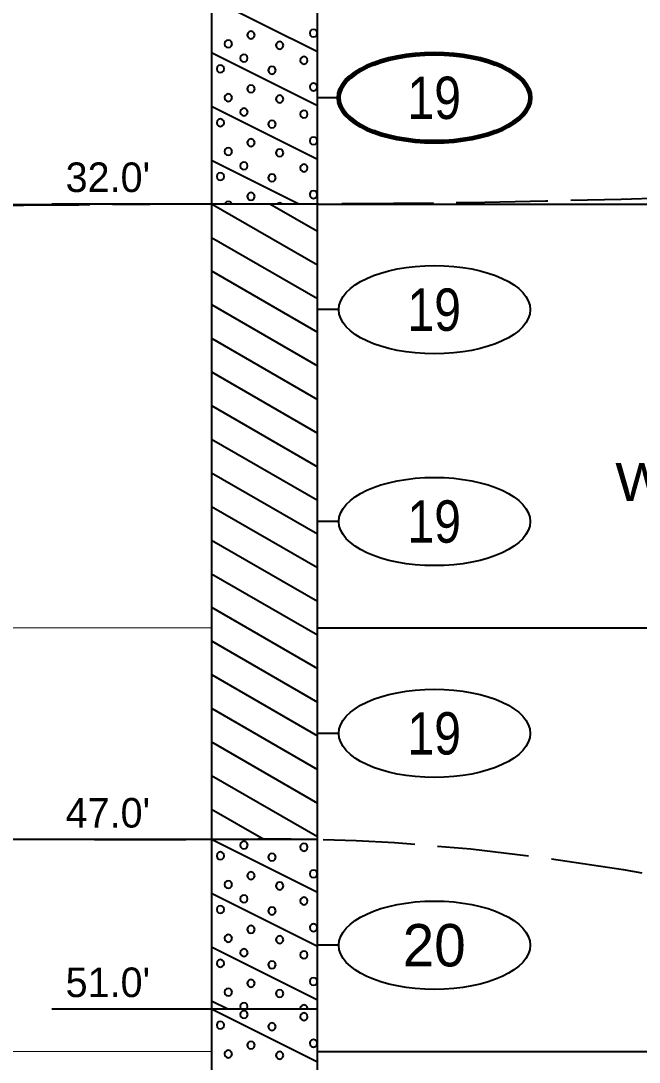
# Model space of a CAD drawing. Extents: x -76 to 974, y -1080 to -735.
# Drawn here: x 281.69 to 296.27, y -982.34 to -957.76 of the extents above; entities that cross this region are included whole.
import ezdxf
from ezdxf.enums import TextEntityAlignment as Align

# ---------------------------------------------------------------- set-up
doc = ezdxf.new("R2010")
doc.units = 0
doc.header["$LTSCALE"] = 0.36
doc.linetypes.add('LONG_DASHED', pattern=[7.5, 6, -1.5])
for name, color, linetype, lineweight in [('27', 7, 'Continuous', 40), ('28', 7, 'LONG_DASHED', 60), ('7', 7, 'Continuous', 13)]:
    doc.layers.add(name, color=color, linetype=linetype, lineweight=lineweight)
doc.layers.add('29', color=7, linetype='Continuous')

msp = doc.modelspace()

# ---------------------------------------------------------------- linework, layer by layer
at = {"layer": '27'}
for p, q in [((286.1855, -947.0789), (286.1855, -962.0789)), ((288.6855, -962.0789), (288.6855, -947.0789)), ((286.1855, -957.2389), (288.6855, -958.4889)), ((286.1855, -958.5089), (288.6855, -959.7589)), ((289.1855, -959.5789), (288.6855, -959.5789)), ((286.1855, -959.7789), (288.6855, -961.0289)), ((286.1855, -961.0489), (288.2455, -962.0789)), ((282.4181, -962.0789), (286.1855, -962.0789)), ((286.1855, -962.0789), (288.6855, -962.0789)), ((286.1855, -962.0789), (288.6855, -963.5223)), ((286.1855, -962.0789), (286.1855, -977.0789)), ((287.5603, -962.0789), (288.6855, -962.7286)), ((287.5603, -962.0789), (288.6855, -962.7286)), ((288.6855, -977.0789), (288.6855, -962.0789)), ((288.6855, -962.09), (321.1855, -962.09)), ((286.1855, -962.8727), (288.6855, -964.3161)), ((286.1855, -962.8727), (288.6855, -964.3161)), ((286.1855, -963.6664), (288.6855, -965.1098)), ((286.1855, -964.4602), (288.6855, -965.9036)), ((286.1855, -964.4602), (288.6855, -965.9036)), ((289.1855, -964.5789), (288.6855, -964.5789)), ((286.1855, -965.2539), (288.6855, -966.6973)), ((286.1855, -966.0477), (288.6855, -967.4911)), ((286.1855, -966.0477), (288.6855, -967.4911)), ((286.1855, -966.8414), (288.6855, -968.2848)), ((286.1855, -967.6352), (288.6855, -969.0786)), ((286.1855, -967.6352), (288.6855, -969.0786)), ((286.1855, -968.4289), (288.6855, -969.8723)), ((286.1855, -969.2227), (288.6855, -970.6661)), ((286.1855, -969.2227), (288.6855, -970.6661)), ((289.1855, -969.5789), (288.6855, -969.5789)), ((286.1855, -970.0164), (288.6855, -971.4598)), ((286.1855, -970.8102), (288.6855, -972.2536)), ((286.1855, -970.8102), (288.6855, -972.2536)), ((286.1855, -971.6039), (288.6855, -973.0473)), ((288.6855, -972.09), (321.1855, -972.09)), ((286.1855, -972.3977), (288.6855, -973.8411)), ((286.1855, -972.3977), (288.6855, -973.8411)), ((286.1855, -973.1914), (288.6855, -974.6348)), ((286.1855, -973.9852), (288.6855, -975.4286)), ((286.1855, -973.9852), (288.6855, -975.4286)), ((289.1855, -974.5789), (288.6855, -974.5789)), ((286.1855, -974.7789), (288.6855, -976.2223)), ((286.1855, -975.5727), (288.6855, -977.0161)), ((286.1855, -975.5727), (288.6855, -977.0161)), ((286.1855, -976.3664), (287.4196, -977.0789)), ((282.4181, -977.0789), (286.1855, -977.0789)), ((286.1855, -977.0789), (288.6855, -977.0789)), ((286.1855, -977.0789), (288.6855, -978.3289)), ((286.1855, -977.0789), (286.1855, -981.0789)), ((288.6855, -981.0789), (288.6855, -977.0789)), ((286.1855, -978.3489), (288.6855, -979.5989)), ((286.1855, -979.6189), (288.6855, -980.8689)), ((289.1855, -979.5789), (288.6855, -979.5789)), ((282.4181, -981.0789), (286.1855, -981.0789)), ((286.1855, -980.8889), (286.5655, -981.0789)), ((286.1855, -981.0789), (288.6855, -981.0789)), ((286.1855, -981.0789), (288.6855, -982.3289)), ((286.1855, -981.0789), (286.1855, -987.0789)), ((288.6855, -987.0789), (288.6855, -981.0789)), ((288.6855, -982.09), (321.1855, -982.09))]:
    msp.add_line(p, q, dxfattribs=at)
for points in [[(288.6773, -958.0542), (288.6654, -958.0097), (288.6329, -957.9772), (288.5884, -957.9653), (288.544, -957.9772), (288.5114, -958.0097), (288.4995, -958.0542), (288.5114, -958.0986), (288.544, -958.1312), (288.5884, -958.1431), (288.6329, -958.1312), (288.6654, -958.0986)], [(286.6674, -958.3059), (286.6555, -958.2614), (286.623, -958.2289), (286.5785, -958.217), (286.5341, -958.2289), (286.5015, -958.2614), (286.4896, -958.3059), (286.5015, -958.3503), (286.5341, -958.3829), (286.5785, -958.3948), (286.623, -958.3829), (286.6555, -958.3503)], [(287.2026, -958.0974), (287.1907, -958.053), (287.1582, -958.0204), (287.1137, -958.0085), (287.0693, -958.0204), (287.0367, -958.053), (287.0248, -958.0974), (287.0367, -958.1419), (287.0693, -958.1744), (287.1137, -958.1863), (287.1582, -958.1744), (287.1907, -958.1419)], [(287.8802, -958.3389), (287.8683, -958.2945), (287.8358, -958.262), (287.7913, -958.25), (287.7469, -958.262), (287.7143, -958.2945), (287.7024, -958.3389), (287.7143, -958.3834), (287.7469, -958.4159), (287.7913, -958.4278), (287.8358, -958.4159), (287.8683, -958.3834)], [(287.0361, -958.6441), (287.0242, -958.5996), (286.9917, -958.5671), (286.9472, -958.5552), (286.9028, -958.5671), (286.8702, -958.5996), (286.8583, -958.6441), (286.8702, -958.6885), (286.9028, -958.721), (286.9472, -958.733), (286.9917, -958.721), (287.0242, -958.6885)], [(288.451, -958.6949), (288.4391, -958.6505), (288.4066, -958.6179), (288.3621, -958.606), (288.3177, -958.6179), (288.2851, -958.6505), (288.2732, -958.6949), (288.2851, -958.7394), (288.3177, -958.7719), (288.3621, -958.7838), (288.4066, -958.7719), (288.4391, -958.7394)], [(286.4831, -958.8958), (286.4712, -958.8513), (286.4386, -958.8188), (286.3942, -958.8069), (286.3497, -958.8188), (286.3172, -958.8513), (286.3053, -958.8958), (286.3172, -958.9402), (286.3497, -958.9728), (286.3942, -958.9847), (286.4386, -958.9728), (286.4712, -958.9402)], [(287.6984, -958.9288), (287.6865, -958.8844), (287.654, -958.8518), (287.6095, -958.8399), (287.5651, -958.8518), (287.5325, -958.8844), (287.5206, -958.9288), (287.5325, -958.9733), (287.5651, -959.0058), (287.6095, -959.0177), (287.654, -959.0058), (287.6865, -958.9733)], [(287.2026, -959.3661), (287.1907, -959.3217), (287.1582, -959.2891), (287.1137, -959.2772), (287.0693, -959.2891), (287.0367, -959.3217), (287.0248, -959.3661), (287.0367, -959.4106), (287.0693, -959.4431), (287.1137, -959.455), (287.1582, -959.4431), (287.1907, -959.4106)], [(288.6773, -959.3229), (288.6654, -959.2785), (288.6329, -959.2459), (288.5884, -959.234), (288.544, -959.2459), (288.5114, -959.2785), (288.4995, -959.3229), (288.5114, -959.3674), (288.544, -959.3999), (288.5884, -959.4118), (288.6329, -959.3999), (288.6654, -959.3674)], [(286.6674, -959.5746), (286.6555, -959.5302), (286.623, -959.4976), (286.5785, -959.4857), (286.5341, -959.4976), (286.5015, -959.5302), (286.4896, -959.5746), (286.5015, -959.6191), (286.5341, -959.6516), (286.5785, -959.6635), (286.623, -959.6516), (286.6555, -959.6191)], [(287.8802, -959.6077), (287.8683, -959.5632), (287.8358, -959.5307), (287.7913, -959.5188), (287.7469, -959.5307), (287.7143, -959.5632), (287.7024, -959.6077), (287.7143, -959.6521), (287.7469, -959.6847), (287.7913, -959.6966), (287.8358, -959.6847), (287.8683, -959.6521)], [(287.0362, -959.9152), (287.0243, -959.8708), (286.9917, -959.8383), (286.9473, -959.8263), (286.9028, -959.8383), (286.8703, -959.8708), (286.8584, -959.9152), (286.8703, -959.9597), (286.9028, -959.9922), (286.9473, -960.0041), (286.9917, -959.9922), (287.0243, -959.9597)], [(288.451, -959.9662), (288.4391, -959.9217), (288.4066, -959.8892), (288.3621, -959.8773), (288.3177, -959.8892), (288.2851, -959.9217), (288.2732, -959.9662), (288.2851, -960.0106), (288.3177, -960.0432), (288.3621, -960.0551), (288.4066, -960.0432), (288.4391, -960.0106)], [(286.4831, -960.167), (286.4712, -960.1226), (286.4386, -960.09), (286.3942, -960.0781), (286.3497, -960.09), (286.3172, -960.1226), (286.3053, -960.167), (286.3172, -960.2115), (286.3497, -960.244), (286.3942, -960.2559), (286.4386, -960.244), (286.4712, -960.2115)], [(287.6984, -960.2001), (287.6865, -960.1556), (287.654, -960.1231), (287.6095, -960.1112), (287.5651, -960.1231), (287.5325, -960.1556), (287.5206, -960.2001), (287.5325, -960.2445), (287.5651, -960.2771), (287.6095, -960.289), (287.654, -960.2771), (287.6865, -960.2445)], [(287.2026, -960.6374), (287.1907, -960.593), (287.1582, -960.5604), (287.1137, -960.5485), (287.0693, -960.5604), (287.0367, -960.593), (287.0248, -960.6374), (287.0367, -960.6819), (287.0693, -960.7144), (287.1137, -960.7263), (287.1582, -960.7144), (287.1907, -960.6819)], [(288.6773, -960.5942), (288.6654, -960.5497), (288.6329, -960.5172), (288.5884, -960.5053), (288.544, -960.5172), (288.5114, -960.5497), (288.4995, -960.5942), (288.5114, -960.6386), (288.544, -960.6712), (288.5884, -960.6831), (288.6329, -960.6712), (288.6654, -960.6386)], [(286.6674, -960.8459), (286.6555, -960.8014), (286.623, -960.7689), (286.5785, -960.757), (286.5341, -960.7689), (286.5015, -960.8014), (286.4896, -960.8459), (286.5015, -960.8903), (286.5341, -960.9229), (286.5785, -960.9348), (286.623, -960.9229), (286.6555, -960.8903)], [(287.8802, -960.8789), (287.8683, -960.8345), (287.8358, -960.802), (287.7913, -960.79), (287.7469, -960.802), (287.7143, -960.8345), (287.7024, -960.8789), (287.7143, -960.9234), (287.7469, -960.9559), (287.7913, -960.9678), (287.8358, -960.9559), (287.8683, -960.9234)], [(287.0361, -961.1841), (287.0242, -961.1396), (286.9917, -961.1071), (286.9472, -961.0952), (286.9028, -961.1071), (286.8702, -961.1396), (286.8583, -961.1841), (286.8702, -961.2285), (286.9028, -961.261), (286.9472, -961.273), (286.9917, -961.261), (287.0242, -961.2285)], [(288.451, -961.2349), (288.4391, -961.1905), (288.4066, -961.1579), (288.3621, -961.146), (288.3177, -961.1579), (288.2851, -961.1905), (288.2732, -961.2349), (288.2851, -961.2794), (288.3177, -961.3119), (288.3621, -961.3238), (288.4066, -961.3119), (288.4391, -961.2794)], [(286.4831, -961.4358), (286.4712, -961.3913), (286.4386, -961.3588), (286.3942, -961.3469), (286.3497, -961.3588), (286.3172, -961.3913), (286.3053, -961.4358), (286.3172, -961.4802), (286.3497, -961.5128), (286.3942, -961.5247), (286.4386, -961.5128), (286.4712, -961.4802)], [(287.6984, -961.4688), (287.6865, -961.4244), (287.654, -961.3918), (287.6095, -961.3799), (287.5651, -961.3918), (287.5325, -961.4244), (287.5206, -961.4688), (287.5325, -961.5133), (287.5651, -961.5458), (287.6095, -961.5577), (287.654, -961.5458), (287.6865, -961.5133)], [(287.2026, -961.9061), (287.1907, -961.8617), (287.1582, -961.8291), (287.1137, -961.8172), (287.0693, -961.8291), (287.0367, -961.8617), (287.0248, -961.9061), (287.0367, -961.9506), (287.0693, -961.9831), (287.1137, -961.995), (287.1582, -961.9831), (287.1907, -961.9506)], [(288.6773, -961.8629), (288.6654, -961.8185), (288.6329, -961.7859), (288.5884, -961.774), (288.544, -961.7859), (288.5114, -961.8185), (288.4995, -961.8629), (288.5114, -961.9074), (288.544, -961.9399), (288.5884, -961.9518), (288.6329, -961.9399), (288.6654, -961.9074)], [(286.6555, -962.0702), (286.623, -962.0376), (286.5785, -962.0257), (286.5341, -962.0376), (286.5015, -962.0702), (286.4992, -962.0789), (286.6579, -962.0789)], [(287.8358, -962.0707), (287.7913, -962.0588), (287.7469, -962.0707), (287.7386, -962.0789), (287.844, -962.0789)], [(287.0362, -977.2152), (287.0243, -977.1708), (286.9917, -977.1383), (286.9473, -977.1263), (286.9028, -977.1383), (286.8703, -977.1708), (286.8584, -977.2152), (286.8703, -977.2597), (286.9028, -977.2922), (286.9473, -977.3041), (286.9917, -977.2922), (287.0243, -977.2597)], [(286.4831, -977.467), (286.4712, -977.4226), (286.4386, -977.39), (286.3942, -977.3781), (286.3497, -977.39), (286.3172, -977.4226), (286.3053, -977.467), (286.3172, -977.5115), (286.3497, -977.544), (286.3942, -977.5559), (286.4386, -977.544), (286.4712, -977.5115)], [(287.6984, -977.5001), (287.6865, -977.4556), (287.654, -977.4231), (287.6095, -977.4112), (287.5651, -977.4231), (287.5325, -977.4556), (287.5206, -977.5001), (287.5325, -977.5445), (287.5651, -977.5771), (287.6095, -977.589), (287.654, -977.5771), (287.6865, -977.5445)], [(288.451, -977.2662), (288.4391, -977.2217), (288.4066, -977.1892), (288.3621, -977.1773), (288.3177, -977.1892), (288.2851, -977.2217), (288.2732, -977.2662), (288.2851, -977.3106), (288.3177, -977.3432), (288.3621, -977.3551), (288.4066, -977.3432), (288.4391, -977.3106)], [(287.2026, -977.9374), (287.1907, -977.893), (287.1582, -977.8604), (287.1137, -977.8485), (287.0693, -977.8604), (287.0367, -977.893), (287.0248, -977.9374), (287.0367, -977.9819), (287.0693, -978.0144), (287.1137, -978.0263), (287.1582, -978.0144), (287.1907, -977.9819)], [(288.6773, -977.8942), (288.6654, -977.8497), (288.6329, -977.8172), (288.5884, -977.8053), (288.544, -977.8172), (288.5114, -977.8497), (288.4995, -977.8942), (288.5114, -977.9386), (288.544, -977.9712), (288.5884, -977.9831), (288.6329, -977.9712), (288.6654, -977.9386)], [(286.6674, -978.1459), (286.6555, -978.1014), (286.623, -978.0689), (286.5785, -978.057), (286.5341, -978.0689), (286.5015, -978.1014), (286.4896, -978.1459), (286.5015, -978.1903), (286.5341, -978.2229), (286.5785, -978.2348), (286.623, -978.2229), (286.6555, -978.1903)], [(287.8802, -978.1789), (287.8683, -978.1345), (287.8358, -978.102), (287.7913, -978.09), (287.7469, -978.102), (287.7143, -978.1345), (287.7024, -978.1789), (287.7143, -978.2234), (287.7469, -978.2559), (287.7913, -978.2678), (287.8358, -978.2559), (287.8683, -978.2234)], [(287.0361, -978.4841), (287.0242, -978.4396), (286.9917, -978.4071), (286.9472, -978.3952), (286.9028, -978.4071), (286.8702, -978.4396), (286.8583, -978.4841), (286.8702, -978.5285), (286.9028, -978.561), (286.9472, -978.573), (286.9917, -978.561), (287.0242, -978.5285)], [(286.4831, -978.7358), (286.4712, -978.6913), (286.4386, -978.6588), (286.3942, -978.6469), (286.3497, -978.6588), (286.3172, -978.6913), (286.3053, -978.7358), (286.3172, -978.7802), (286.3497, -978.8128), (286.3942, -978.8247), (286.4386, -978.8128), (286.4712, -978.7802)], [(288.451, -978.5349), (288.4391, -978.4905), (288.4066, -978.4579), (288.3621, -978.446), (288.3177, -978.4579), (288.2851, -978.4905), (288.2732, -978.5349), (288.2851, -978.5794), (288.3177, -978.6119), (288.3621, -978.6238), (288.4066, -978.6119), (288.4391, -978.5794)], [(287.6984, -978.7688), (287.6865, -978.7244), (287.654, -978.6918), (287.6095, -978.6799), (287.5651, -978.6918), (287.5325, -978.7244), (287.5206, -978.7688), (287.5325, -978.8133), (287.5651, -978.8458), (287.6095, -978.8577), (287.654, -978.8458), (287.6865, -978.8133)], [(287.2026, -979.2061), (287.1907, -979.1617), (287.1582, -979.1291), (287.1137, -979.1172), (287.0693, -979.1291), (287.0367, -979.1617), (287.0248, -979.2061), (287.0367, -979.2506), (287.0693, -979.2831), (287.1137, -979.295), (287.1582, -979.2831), (287.1907, -979.2506)], [(288.6773, -979.1629), (288.6654, -979.1185), (288.6329, -979.0859), (288.5884, -979.074), (288.544, -979.0859), (288.5114, -979.1185), (288.4995, -979.1629), (288.5114, -979.2074), (288.544, -979.2399), (288.5884, -979.2518), (288.6329, -979.2399), (288.6654, -979.2074)], [(286.6674, -979.4146), (286.6555, -979.3702), (286.623, -979.3376), (286.5785, -979.3257), (286.5341, -979.3376), (286.5015, -979.3702), (286.4896, -979.4146), (286.5015, -979.4591), (286.5341, -979.4916), (286.5785, -979.5035), (286.623, -979.4916), (286.6555, -979.4591)], [(287.8802, -979.4477), (287.8683, -979.4032), (287.8358, -979.3707), (287.7913, -979.3588), (287.7469, -979.3707), (287.7143, -979.4032), (287.7024, -979.4477), (287.7143, -979.4921), (287.7469, -979.5247), (287.7913, -979.5366), (287.8358, -979.5247), (287.8683, -979.4921)], [(287.0362, -979.7552), (287.0243, -979.7108), (286.9917, -979.6783), (286.9473, -979.6663), (286.9028, -979.6783), (286.8703, -979.7108), (286.8584, -979.7552), (286.8703, -979.7997), (286.9028, -979.8322), (286.9473, -979.8441), (286.9917, -979.8322), (287.0243, -979.7997)], [(288.451, -979.8062), (288.4391, -979.7617), (288.4066, -979.7292), (288.3621, -979.7173), (288.3177, -979.7292), (288.2851, -979.7617), (288.2732, -979.8062), (288.2851, -979.8506), (288.3177, -979.8832), (288.3621, -979.8951), (288.4066, -979.8832), (288.4391, -979.8506)], [(286.4831, -980.007), (286.4712, -979.9626), (286.4386, -979.93), (286.3942, -979.9181), (286.3497, -979.93), (286.3172, -979.9626), (286.3053, -980.007), (286.3172, -980.0515), (286.3497, -980.084), (286.3942, -980.0959), (286.4386, -980.084), (286.4712, -980.0515)], [(287.6984, -980.0401), (287.6865, -979.9956), (287.654, -979.9631), (287.6095, -979.9512), (287.5651, -979.9631), (287.5325, -979.9956), (287.5206, -980.0401), (287.5325, -980.0845), (287.5651, -980.1171), (287.6095, -980.129), (287.654, -980.1171), (287.6865, -980.0845)], [(288.6773, -980.4342), (288.6654, -980.3897), (288.6329, -980.3572), (288.5884, -980.3453), (288.544, -980.3572), (288.5114, -980.3897), (288.4995, -980.4342), (288.5114, -980.4786), (288.544, -980.5112), (288.5884, -980.5231), (288.6329, -980.5112), (288.6654, -980.4786)], [(286.6674, -980.6859), (286.6555, -980.6414), (286.623, -980.6089), (286.5785, -980.597), (286.5341, -980.6089), (286.5015, -980.6414), (286.4896, -980.6859), (286.5015, -980.7303), (286.5341, -980.7629), (286.5785, -980.7748), (286.623, -980.7629), (286.6555, -980.7303)], [(287.2026, -980.4774), (287.1907, -980.433), (287.1582, -980.4004), (287.1137, -980.3885), (287.0693, -980.4004), (287.0367, -980.433), (287.0248, -980.4774), (287.0367, -980.5219), (287.0693, -980.5544), (287.1137, -980.5663), (287.1582, -980.5544), (287.1907, -980.5219)], [(287.8802, -980.7189), (287.8683, -980.6745), (287.8358, -980.642), (287.7913, -980.63), (287.7469, -980.642), (287.7143, -980.6745), (287.7024, -980.7189), (287.7143, -980.7634), (287.7469, -980.7959), (287.7913, -980.8078), (287.8358, -980.7959), (287.8683, -980.7634)], [(287.0242, -981.0685), (287.0361, -981.0241), (287.0242, -980.9796), (286.9917, -980.9471), (286.9472, -980.9352), (286.9028, -980.9471), (286.8702, -980.9796), (286.8583, -981.0241), (286.8702, -981.0685), (286.8806, -981.0789), (287.0138, -981.0789)], [(288.451, -981.0749), (288.4391, -981.0305), (288.4066, -980.9979), (288.3621, -980.986), (288.3177, -980.9979), (288.2851, -981.0305), (288.2732, -981.0749), (288.2743, -981.0789), (288.45, -981.0789)], [(287.0362, -981.2152), (287.0243, -981.1708), (286.9917, -981.1383), (286.9473, -981.1263), (286.9028, -981.1383), (286.8703, -981.1708), (286.8584, -981.2152), (286.8703, -981.2597), (286.9028, -981.2922), (286.9473, -981.3041), (286.9917, -981.2922), (287.0243, -981.2597)], [(288.451, -981.2662), (288.4391, -981.2217), (288.4066, -981.1892), (288.3621, -981.1773), (288.3177, -981.1892), (288.2851, -981.2217), (288.2732, -981.2662), (288.2851, -981.3106), (288.3177, -981.3432), (288.3621, -981.3551), (288.4066, -981.3432), (288.4391, -981.3106)], [(286.4831, -981.467), (286.4712, -981.4226), (286.4386, -981.39), (286.3942, -981.3781), (286.3497, -981.39), (286.3172, -981.4226), (286.3053, -981.467), (286.3172, -981.5115), (286.3497, -981.544), (286.3942, -981.5559), (286.4386, -981.544), (286.4712, -981.5115)], [(287.6984, -981.5001), (287.6865, -981.4556), (287.654, -981.4231), (287.6095, -981.4112), (287.5651, -981.4231), (287.5325, -981.4556), (287.5206, -981.5001), (287.5325, -981.5445), (287.5651, -981.5771), (287.6095, -981.589), (287.654, -981.5771), (287.6865, -981.5445)], [(288.6773, -981.8942), (288.6654, -981.8497), (288.6329, -981.8172), (288.5884, -981.8053), (288.544, -981.8172), (288.5114, -981.8497), (288.4995, -981.8942), (288.5114, -981.9386), (288.544, -981.9712), (288.5884, -981.9831), (288.6329, -981.9712), (288.6654, -981.9386)], [(286.6674, -982.1459), (286.6555, -982.1014), (286.623, -982.0689), (286.5785, -982.057), (286.5341, -982.0689), (286.5015, -982.1014), (286.4896, -982.1459), (286.5015, -982.1903), (286.5341, -982.2229), (286.5785, -982.2348), (286.623, -982.2229), (286.6555, -982.1903)], [(287.2026, -981.9374), (287.1907, -981.893), (287.1582, -981.8604), (287.1137, -981.8485), (287.0693, -981.8604), (287.0367, -981.893), (287.0248, -981.9374), (287.0367, -981.9819), (287.0693, -982.0144), (287.1137, -982.0263), (287.1582, -982.0144), (287.1907, -981.9819)], [(287.8802, -982.1789), (287.8683, -982.1345), (287.8358, -982.102), (287.7913, -982.09), (287.7469, -982.102), (287.7143, -982.1345), (287.7024, -982.1789), (287.7143, -982.2234), (287.7469, -982.2559), (287.7913, -982.2678), (287.8358, -982.2559), (287.8683, -982.2234)]]:
    msp.add_lwpolyline(points, close=True, dxfattribs=at)
at = {"layer": '27', "lineweight": 100}
msp.add_ellipse((291.4429, -959.5789), major_axis=(2.2574, 0), ratio=0.461538, dxfattribs=at)
at = {"layer": '27'}
for centre in [(291.4429, -964.5789), (291.4429, -969.5789), (291.4429, -974.5789), (291.4429, -979.5789)]:
    msp.add_ellipse(centre, major_axis=(2.2574, 0), ratio=0.461538, dxfattribs=at)
at = {"layer": '28', "lineweight": 40}
for points in [[(273.0575, -962.107), (282.3308, -962.107), (286.1855, -962.0789), (288.6855, -962.0789), (317.3293, -961.3789), (321.0966, -961.3789), (323.6855, -961.3789), (336.4253, -961.3789)], [(272.6207, -977.1334), (282.4181, -977.0789), (286.1855, -977.0789), (288.6855, -977.0789), (317.4181, -981.3789), (321.2744, -981.3789), (323.6855, -981.3789), (336.5553, -981.3789)]]:
    msp.add_spline(points, degree=3, dxfattribs=at)
at = {"layer": '7'}
for p, q in [((256.2421, -962.09), (286.1855, -962.09)), ((256.2421, -972.09), (286.1855, -972.09)), ((256.2421, -982.09), (286.1855, -982.09))]:
    msp.add_line(p, q, dxfattribs=at)

# ---------------------------------------------------------------- texts
at = {"layer": '27', "width": 0.85}
for p in [(291.4355, -960.0788), (291.4355, -965.0788), (291.4355, -970.0788), (291.4355, -975.0788)]:
    msp.add_text('19', height=1, dxfattribs=at).set_placement(p, align=Align.CENTER)
at = {"layer": '27'}
for s, p in [("32.0'", (282.7421, -961.8025)), ("47.0'", (282.7421, -976.8025)), ("51.0'", (282.7421, -980.8025))]:
    msp.add_text(s, height=0.6976, dxfattribs=at).set_placement(p)
msp.add_text('20', height=1, dxfattribs=at).set_placement((291.4356, -980.0788), align=Align.CENTER)
at = {"layer": '29', "width": 1.1}
msp.add_text('WITH TRACE OF SHELL MATERIAL', height=0.9, dxfattribs=at).set_placement((306.7031, -969.0969), align=Align.CENTER)

doc.saveas('drawing.dxf')
